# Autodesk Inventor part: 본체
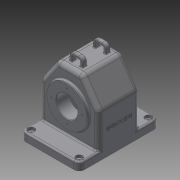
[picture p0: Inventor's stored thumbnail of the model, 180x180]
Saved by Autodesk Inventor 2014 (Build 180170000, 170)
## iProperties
Created: 2016-12
Part Number: 본체
Material: 일반
Document SubType Name: Modeling
Designer: owner
Density: 1 g/cm^3
Appearance: 기본값
Author: owner
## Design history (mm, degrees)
sketch "스케치1"
  geometry: L1 (55, -65)-(-55, -65); L2 (-55, -65)-(-55, 15); L3 (-55, 15)-(-23.491, 60); L4 (-23.491, 60)-(23.491, 60); L5 (23.491, 60)-(55, 15); L6 (55, 15)-(55, -65); 2 further points
  constraints: 12 end point, 2 parallel, 1 horizontal, 1 midpoint, 1 perpendicular, 1 vertical alignment
  dimensions: "d0" = 35 deg angle of L2 L3; "d1" = 35 deg angle of L6 L5; "d2" = 110 distance of L1.start L1.end; "d3" = 65 distance from line of L1 point (0, 0); "d5" = 80 distance of L1.end L2.end; "d6" = 80 distance from line of L1 L5.end; "d8" = 125 distance between parallel lines of L1 L4
extrude "돌출1" new body sketch "스케치1" stored distance "d9" = 77; taper "d10" = 0 deg
sketch "스케치2"
  geometry: L1 (110, -77)-(110, 0) reference; L2 (0, 0)-(110, 0) reference; L3 (0, 0)-(0, -77) reference; L4 (110, -77)-(0, -77) reference; L5 (0, 36.5)-(110, 36.5); L6 (110, 36.5)-(110, -113.5); L7 (110, -113.5)-(0, -113.5); L8 (0, -113.5)-(0, 36.5); L9 (0, 36.5)-(110, -113.5); L10 (110, 36.5)-(0, -113.5); 1 further point
  constraints: 12 end point, 2 midpoint, 2 parallel, 1 horizontal, 1 perpendicular
  dimensions: "d11" = 110 distance of L6.end L7.end; "d12" = 150 distance of L5.end L6.end
extrude "돌출2" join sketch "스케치2" distance "d13" = 15; taper "d14" = 0 deg
sketch "스케치3"
  geometry: C1 r 37.5 at (0, 0); 1 further point
  constraints: 1 centre point, 1 coincident
  dimensions: "d15" = 75 diameter of C1
extrude "돌출3" join sketch "스케치3" distance "d16" = 5; taper "d17" = 0 deg
sketch "스케치4"
  geometry: C1 r 31 at (0, 0); 1 further point
  constraints: 1 centre point, 1 coincident
  dimensions: "d18" = 62 diameter of C1
extrude "돌출4" join sketch "스케치4" distance "d19" = 10; taper "d20" = 0 deg
sketch "스케치5"
  geometry: L1 (-55, -65)-(-55, 15) reference; L2 (-55, 15)-(-23.491, 60) reference; L3 (-23.491, 60)-(23.491, 60) reference; L4 (23.491, 60)-(55, 15) reference; L5 (55, 15)-(55, -65) reference; L6 (55, -65)-(-55, -65) reference; L7 (-20.888, 55)-(-50, 13.424); L8 (-50, 13.424)-(-50, -65); L9 (50, -65)-(50, 13.424); L10 (50, 13.424)-(20.888, 55); L11 (20.888, 55)-(-20.888, 55); 1 further point
  constraints: 10 end point, 2 point on line, 3 other
  dimensions: "d21" = 5 distance between parallel lines of L1 L8; "d22" = 5 distance between parallel lines of L5 L9
extrude "돌출5" cut sketch "스케치5" stored distance "d23" = 67; taper "d24" = 0 deg
sketch "스케치6"
  geometry: L1 (60, 38.5)-(15, 38.5) reference; L2 (55, 33.5)-(13.424, 33.5) reference; L3 (0, 105)-(0, -105) reference; L4 (-37.5, 38.5)-(37.5, 38.5) reference; L5 (0, 19.5)-(27, 19.5); L6 (27, 19.5)-(41, 33.5); L7 (41, 33.5)-(0, 33.5); L8 (37.5, 43.5)-(-37.5, 43.5) reference; 1 further point
  constraints: 6 end point, 2 point on line, 1 parallel, 1 perpendicular
  dimensions: "d25" = 24 distance between parallel lines of L8 L5; "d26" = 45 deg angle of L5 L6; "d27" = 5 distance between parallel lines of L1 L7; "d28" = 27 distance of L5.start L5.end
revolve "회전1" sketch "스케치6" stored, may be unused: angle "d29" = 90 deg
sketch "스케치7"
  geometry: C1 r 37.5 at (0, 0) reference; C2 r 20 at (0, 0)
  constraints: 1 centre point, 1 coincident
  dimensions: "d30" = 40 diameter of C2
extrude "돌출6" cut sketch "스케치7" stored distance "d31" = 67; taper "d32" = 0 deg
node "작업 평면1"
sketch "스케치8"
  geometry: L1 (23.491, 60)-(-23.491, 60) reference; L2 (-55, -50)-(55, -50) reference; L3 (55, -50)-(55, 15) reference; L4 (55, 15)-(23.491, 60) reference; L5 (23.491, 60)-(-23.491, 60) reference; L6 (-23.491, 60)-(-55, 15) reference; L7 (-55, 15)-(-55, -50) reference; L8 (-12.5, 60)-(-12.5, 75); L9 (-12.5, 75)-(12.5, 75); L10 (12.5, 75)-(12.5, 60); L11 (7.5, 60)-(7.5, 70); L12 (7.5, 70)-(-7.5, 70); L13 (-7.5, 70)-(-7.5, 60); L14 (50, -65)-(-50, -65) reference; C1 r 37.5 at (0, 0) reference; 2 further points
  constraints: 12 end point, 4 perpendicular, 4 point on line, 2 parallel, 1 midpoint, 1 vertical alignment
  dimensions: "d34" = 25 distance of L8.end L9.end; "d35" = 15 distance between parallel lines of L11 L13; "d36" = 5 distance between parallel lines of L13 L8; "d38" = 140 distance between parallel lines of L14 L9; "d39" = 5 distance between parallel lines of L9 L12
extrude "돌출7" join sketch "스케치8" distance "d40" = 8; taper "d41" = 0 deg
fillet "모깎기1" dims "d42" = 8
fillet "모깎기2" dims "d43" = 1
fillet "모깎기3" dims "d44" = 1
fillet "모깎기4" dims "d45" = 10
sketch "스케치9"
  geometry: A1 r 10 centre (10, 103.5) between (10, 113.5) and (0, 103.5) reference; A2 r 10 centre (100, 103.5) between (110, 103.5) and (100, 113.5) reference; A3 r 10 centre (10, -26.5) between (0, -26.5) and (10, -36.5) reference; A4 r 10 centre (100, -26.5) between (100, -36.5) and (110, -26.5) reference; 5 further points
  constraints: 4 coincident
hole "구멍1" sketch "스케치9" at (10, 103.5), (100, 103.5), (100, -26.5), (10, -26.5) diameter "d46" = 5; stored, may be unused: countersink angle "d50" = 90 deg, drill point angle "d52" = 118 deg; dims "d47" = 6, "d48" = 12, "d49" = 5, "d51" = 8
sketch "스케치10"
  geometry: C1 r 20 at (0, 0) reference; 1 further point
  constraints: 1 vertical alignment
  dimensions: "d53" = 29 distance of point (0, 29) C1.centre
hole "구멍2" sketch "스케치10" at (0, 29) diameter "d54" = 2.459; stored, may be unused: countersink angle "d58" = 90 deg, drill point angle "d60" = 118 deg; dims "d55" = 6, "d56" = 4, "d57" = 2, "d59" = 8
sketch "스케치11"
  geometry: C1 r 20 at (0, 0) reference; 1 further point
  constraints: 1 vertical alignment
  dimensions: "d64" = 26 distance of C1.centre point (0, 26)
hole "구멍3" sketch "스케치11" at (0, 26) diameter "d65" = 2.459; stored, may be unused: countersink angle "d69" = 90 deg, drill point angle "d71" = 118 deg; dims "d66" = 6, "d67" = 4, "d68" = 2, "d70" = 8
fillet "모깎기5" dims "d75" = 10
fillet "모깎기6" dims "d76" = 8
fillet "모깎기7" dims "d77" = 3
fillet "모깎기8" dims "d78" = 3
fillet "모깎기9" dims "d79" = 3
fillet "모깎기10" dims "d80" = 1
fillet "모깎기11" dims "d81" = 3
chamfer "모따기1" distance "d82" = 1; stored, may be unused: second distance "d83" = 2, angle "d84" = 45 deg
fillet "모깎기12" dims "d85" = 3
fillet "모깎기13" dims "d86" = 3
fillet "모깎기14" dims "d87" = 3
node "작업 평면2"
sketch "스케치12"
  geometry: L1 (11.847, 38.5)-(-47, 38.5) reference; L2 (-65, -65)-(-65, 65) reference; 2 further points
  constraints: 1 other
  dimensions: "d89" = 38.5 distance from line of point (-20, 0) L1; "d90" = 45 distance from line of point (-20, 0) L2
feature "엠보싱1" sketch "스케치12" dims "d0" = 35 deg, "d1" = 35 deg, "d2" = 110, "d3" = 65, "d5" = 80, "d6" = 80, "d8" = 125, "d11" = 110, "d12" = 150, "d91" = 0.5, "d92" = 0
fillet "모깎기15" dims "d93" = 1
fillet "모깎기16" dims "d94" = 1
node "솔리드1"
mirror "대칭1"
pattern_circular "원형 패턴1" dims angle "d62" = 360 deg
pattern_circular "원형 패턴2" dims angle "d73" = 360 deg
node "투영된 루프1"
node "절단 모서리 투영1"
other parameters: "d33" = 26, "d88" = 94.25
